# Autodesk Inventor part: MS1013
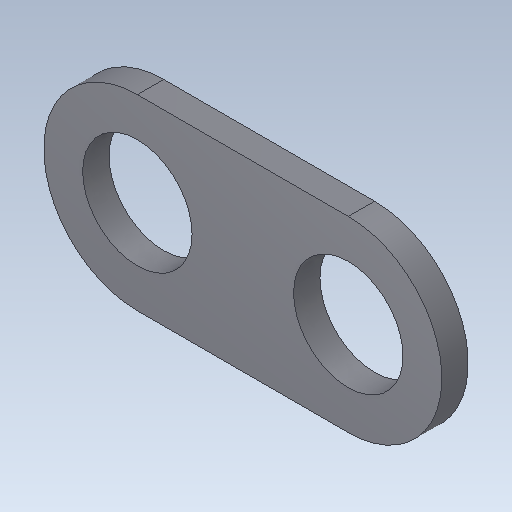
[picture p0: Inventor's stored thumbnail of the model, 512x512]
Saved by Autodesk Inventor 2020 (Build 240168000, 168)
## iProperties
Created: 2015-11
Part Number: MS1013
Material: Ogólny
Document SubType Name: Modeling
Designer: Tomasz
Density: 1 g/cm^3
Appearance: Domyślna
Sending System: SolidWorks 2017
Last Author: Tomasz
Last Saved: 2017-09-17
Author: Tomasz
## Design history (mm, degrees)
feature "Imported1"
node "Bryła1"
